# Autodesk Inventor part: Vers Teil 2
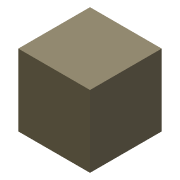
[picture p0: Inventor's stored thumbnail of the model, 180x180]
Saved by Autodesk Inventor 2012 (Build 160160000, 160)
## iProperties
Created: 2004-10
Part Number: Vers Teil 2
Document SubType Name: Modeling
Designer: jukr
Manufacturer: Standard
Standards Organization: Custom
Density: 1 g/cm^3
Material: Standard
Author: jukr
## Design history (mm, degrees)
sketch "Skizze1"
  geometry: L1 (109.783, -55.473)-(159.783, -55.473); L2 (159.783, -55.473)-(159.783, -5.473); L3 (159.783, -5.473)-(109.783, -5.473); L4 (109.783, -5.473)-(109.783, -55.473)
  constraints: 8 end point, 2 parallel, 1 horizontal, 1 perpendicular
  dimensions: "d0" = 50 distance of L2.end L3.end; "d1" = 50 distance of L3.end L1.start (= d0)
extrude "Extrusion1" new body sketch "Skizze1" distance "d2" = 50; taper "d3" = 0 deg
node "Volumenkörper1"
node "Volumenkörpern"
node "Oberflächenkörpern"
